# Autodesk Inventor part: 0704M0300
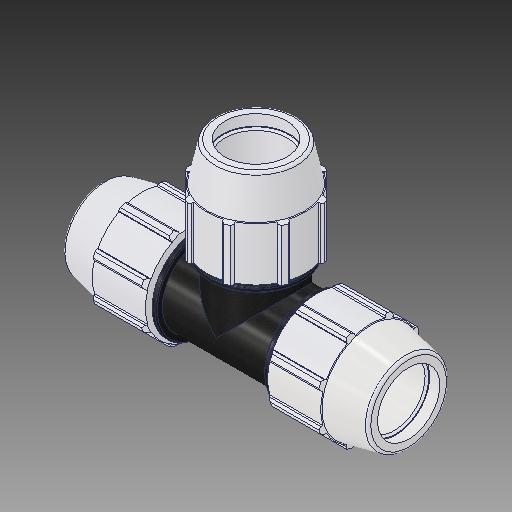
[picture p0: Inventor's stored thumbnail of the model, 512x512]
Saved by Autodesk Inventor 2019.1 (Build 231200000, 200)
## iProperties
Created: 2017-02
Part Number: 0704M0300
Material: PVC-Piping
Description: PLASSON TEE 3'' - 3'' - 3''
Document SubType Name: Modeling
Designer: KIM
Mass: 92.6774 g
Surface Area: 199.44 cm^2
Volume: 66.1981 cm^3
Density: 1.4 g/cm^3
Appearance: PTFE
Author: KIM
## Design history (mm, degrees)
derived "0704M0.ipt"
feature "Solid1::0704M0.ipt"
tag "TaggingFeature1"
body "Solid1"
other parameters: "d2" = 88.7, "d4" = 18.161, "d5" = 54.483, "d7" = 151.892, "d11" = 7.2644, "d13" = 120 deg, "d14" = 115.31, "d15" = 12 deg, "d16" = 132.14604, "d18" = 4.435, "d19" = 35 deg, "d20" = 17.5 deg, "d21" = 141.25956, "d23" = 0, "d25" = 360 deg, "d27" = 3.03784, "d33" = 1.774, "d42" = 76.2762, "d43" = 4.55676, "d46" = 2.661, "d63" = 163.068, "d67" = 113.919, "d76" = 88.7, "d77" = 151.892, "d78" = 12 deg, "d79" = 217.932, "d80" = 120 deg, "d81" = 115.31, "d82" = 18.161, "d85" = 113.919, "d86" = 132.14604, "d87" = 7.2644, "d88" = 7.2644, "d89" = 54.483, "d90" = 76.2762, "d96" = 21.7932, "d98" = 141.25956, "d99" = 35 deg, "d100" = 17.5 deg, "d102" = 0, "d103" = 3.03784, "d107" = 360 deg, "d109" = 2.661, "d112" = 4.435, "d118" = 360 deg, "d121" = 0, "d128" = 435.864, "d131" = 79.83, "d132" = 79.83, "d133" = 163.068, "d134" = 3.26136, "d135" = 21.7932, "d152" = 0, "d154" = 0, "d156" = 0, "d158" = 0, "d_" = 88.7, "E_" = 151.892, "A_" = 217.932, "l_" = 163.068, "H_" = 435.864
